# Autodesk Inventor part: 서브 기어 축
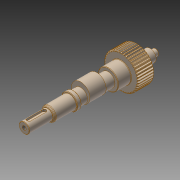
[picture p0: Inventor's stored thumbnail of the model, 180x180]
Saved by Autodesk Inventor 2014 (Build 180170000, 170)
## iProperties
Created: 2018-12
Part Number: 서브 기어 축
Material: 강철, 연강
Document SubType Name: Modeling
Designer: mduedu
Categories: <?xml version="1.0" encoding="UTF-16"?> <MemberInstance><Categories><FamilyTemplate><FamilyTemplateParameter ValueType="xs:double" Id="1" ObjectReferenceKey="da
Density: 7.86 g/cm^3
Mass: 484.999 g
Surface Area: 155.104 cm^2
Volume: 61.7047 cm^3
Appearance: 기본값(1)
Author: mduedu
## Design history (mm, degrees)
sketch "Sketch1"
  geometry: C1 r 21.3 at (0, 0)
  constraints: 1 centre point
  dimensions: "d0" = 42.6 diameter of C1 (= da_da)
extrude "Extrusion1" new body sketch "Sketch1" distance "d1" = 20 (= da_b); taper "d2" = 0 deg
workplane "Work Plane2"
sketch "Sketch2"
  geometry: C1 r 21.3 at (0, 0) reference; C2 r 20.5 at (0, 0)
  constraints: 1 centre point, 1 coincident
  dimensions: "d3" = 41 diameter of C2 (= da_dw)
feature "피치 지름" sketch "Sketch2" dims "d4" = 10, "d5" = 0
workplane "Work Plane8"
workplane "Work Plane9"
chamfer "모따기1" distance "d49" = 1; stored, may be unused: second distance "d50" = 2, angle "d51" = 45 deg
sketch "스케치3"
  geometry: C1 r 12.5 at (0, 0); 1 further point
  constraints: 1 centre point, 1 coincident
  dimensions: "d52" = 25 diameter of C1
extrude "돌출2" join sketch "스케치3" distance "d53" = 16; taper "d54" = 0 deg
sketch "스케치4"
  geometry: C1 r 8.5 at (0, 0); 1 further point
  constraints: 1 centre point, 1 coincident
  dimensions: "d55" = 17 diameter of C1
extrude "돌출3" join sketch "스케치4" distance "d56" = 104; taper "d57" = 0 deg
sketch "스케치5"
  geometry: C1 r 7.5 at (0, 0); 1 further point
  constraints: 1 centre point, 1 coincident
  dimensions: "d58" = 15 diameter of C1
extrude "돌출4" join sketch "스케치5" distance "d59" = 16; taper "d60" = 0 deg
sketch "스케치6"
  geometry: C1 r 4 at (0, 0); 1 further point
  constraints: 1 centre point, 1 coincident
  dimensions: "d61" = 8 diameter of C1
extrude "돌출5" join sketch "스케치6" distance "d62" = 7; taper "d63" = 0 deg
fillet "모깎기1" dims "d67" = 0.5
feature "스퍼 기어" dims "da_b" = 20, "da_d" = 41, "da_aw" = 31, "da_da" = 42.6, "da_df" = 39.086, "da_dw" = 41, angle "da_beta" = 0 deg, "da_lefttooth" = 0, "da_righttooth" = 0
node "작업 평면11"
sketch "스케치7"
  geometry: C1 r 11.5 at (0, 3); C2 r 8.5 at (0, 0) reference; 1 further point
  constraints: 1 centre point, 1 tangent, 1 vertical alignment
  dimensions: "d69" = 3 distance of point (0, 0) C1.centre; "d70" = 23 diameter of C1 (derived)
extrude "돌출6" join sketch "스케치7" stored distance "d71" = 20; taper "d72" = 0 deg
node "작업 평면12"
sketch "스케치8"
  geometry: C1 r 12.5 at (0, 0) reference; C2 r 10 at (0, 0); 1 further point
  constraints: 1 centre point, 1 coincident
  dimensions: "d110" = 20 diameter of C2
extrude "돌출7" join sketch "스케치8" distance "d74" = 5; taper "d75" = 0 deg
sketch "스케치14"
  geometry: L1 (-11.5, 111)-(-6.5, 111); L2 (-6.5, 111)-(-6.5, 140); L3 (-6.5, 140)-(-11.5, 140); L4 (-11.5, 140)-(-11.5, 111); L5 (8.5, 140)-(-8.5, 140) reference; L6 (0, 0)-(0, 140)
  constraints: 10 end point, 2 parallel, 1 collinear, 1 horizontal, 1 midpoint, 1 perpendicular
  dimensions: "d92" = 29 distance between parallel lines of L1 L5; "d93" = 13 diameter of L2 L6; "d95" = 5 distance of L2.end L3.end
revolve "회전2" sketch "스케치14" stored, may be unused: angle "d96" = 90 deg
chamfer "모따기4" distance "d97" = 0.5; stored, may be unused: second distance "d98" = 2, angle "d99" = 45 deg
node "작업 평면13"
sketch "스케치11"
  geometry: L1 (-2.5, 9)-(-2.5, -10); L2 (2.5, -10)-(2.5, 9); L3 (-6, 14.5)-(6, 14.5) reference; A1 r 2.5 centre (0, 9) between (2.5, 9) and (-2.5, 9); A2 r 2.5 centre (0, -10) between (-2.5, -10) and (2.5, -10); 1 further point
  constraints: 4 end point, 4 point on circle, 4 tangent, 2 centre point, 2 vertical alignment, 1 parallel
  dimensions: "d84" = 24 dimension on A2 A1; "d85" = 5 distance between parallel lines of L1 L2; "d108" = 3 distance edge to line of A1 L3
extrude "돌출8" cut sketch "스케치11" distance "d86" = 3; taper "d87" = 0 deg
sketch "스케치12" dims "d88" = 32
  geometry: C1 r 0.5 at (0, -16); 2 further points
  constraints: 2 vertical alignment, 1 centre point, 1 coincident, 2 other
  dimensions: "d89" = 1 diameter of C1
extrude "돌출9" join sketch "스케치12" distance "d90" = 0.3; taper "d91" = 0 deg
sketch "스케치13"
  geometry: C1 r 11.5 at (0, 3) reference; 1 further point
  node "절단 모서리 투영1"
sketch "스케치15"
  geometry: L1 (-8.5, 109.181)-(-7.45, 111); L2 (-8.5, 111)-(8.5, 111) reference; L3 (-8.5, 84)-(-8.5, 111) reference; L4 (0, 0)-(0, 111); L5 (-7.45, 111)-(-8.5, 111); L6 (-8.5, 109.181)-(-8.5, 111)
  constraints: 8 end point, 2 collinear, 2 point on line, 1 midpoint
  dimensions: "d103" = 14.9 diameter of L1.end L4; "d104" = 30 deg angle of L3 L1
revolve "회전3" sketch "스케치15" stored, may be unused: angle "d105" = 90 deg
fillet "모깎기2" dims "d106" = 2
fillet "모깎기3" dims "d107" = 1
chamfer "모따기5" distance "d112" = 0.5; stored, may be unused: second distance "d113" = 2, angle "d114" = 45 deg
hole "구멍1" diameter "d117" = 4.917; stored, may be unused: countersink angle "d121" = 90 deg, drill point angle "d123" = 118 deg; dims "d118" = 12, "d119" = 4, "d120" = 2, "d122" = 14, "d124" = 10, "d125" = 10
body "Solid1"
body "Srf1"
node "투영된 루프1"
other parameters: "d16" = 31 (= da_aw), "d17" = 0, "d34" = 0.76624 (computed from da_z), "d39" = 0, "d41" = 0, "d43" = 31 (= da_aw), "d46" = 31 (= da_aw), "d47" = 0, "d48" = 0
